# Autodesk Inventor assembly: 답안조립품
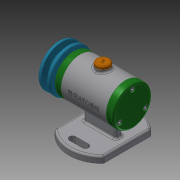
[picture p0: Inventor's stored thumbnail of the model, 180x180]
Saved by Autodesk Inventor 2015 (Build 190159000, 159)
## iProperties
Created: 2021-09
Part Number: 답안조립품
Document SubType Name: Assembly
Designer: 1019876
Author: 1019876
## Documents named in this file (14)
- C:\Users\1019876\Desktop\710906V1024\답안조립품.iam
- C:\Users\1019876\Desktop\710906V1024\V벨트풀리.ipt
- C:\Users\1019876\Desktop\710906V1024\너트 M8.ipt
- C:\Users\1019876\Desktop\710906V1024\뒤커버.ipt
- C:\Users\1019876\Desktop\710906V1024\베어링 15x32x9.ipt
- C:\Users\1019876\Desktop\710906V1024\본체.ipt
- C:\Users\1019876\Desktop\710906V1024\볼트 M4x12.ipt
- C:\Users\1019876\Desktop\710906V1024\스프링와셔 8.ipt
- C:\Users\1019876\Desktop\710906V1024\앞커버.ipt
- C:\Users\1019876\Desktop\710906V1024\오일 실 15x25x7.ipt
- C:\Users\1019876\Desktop\710906V1024\와셔 8x17.ipt
- C:\Users\1019876\Desktop\710906V1024\축.ipt
- C:\Users\1019876\Desktop\710906V1024\캡.ipt
- C:\Users\1019876\Desktop\710906V1024\키 3x3.ipt
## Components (1 placed, 1 different names)
1. V벨트풀리:1 — 각도:2
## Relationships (1: Angle 1)
- 각도:2 [Angle]: V벨트풀리:1
